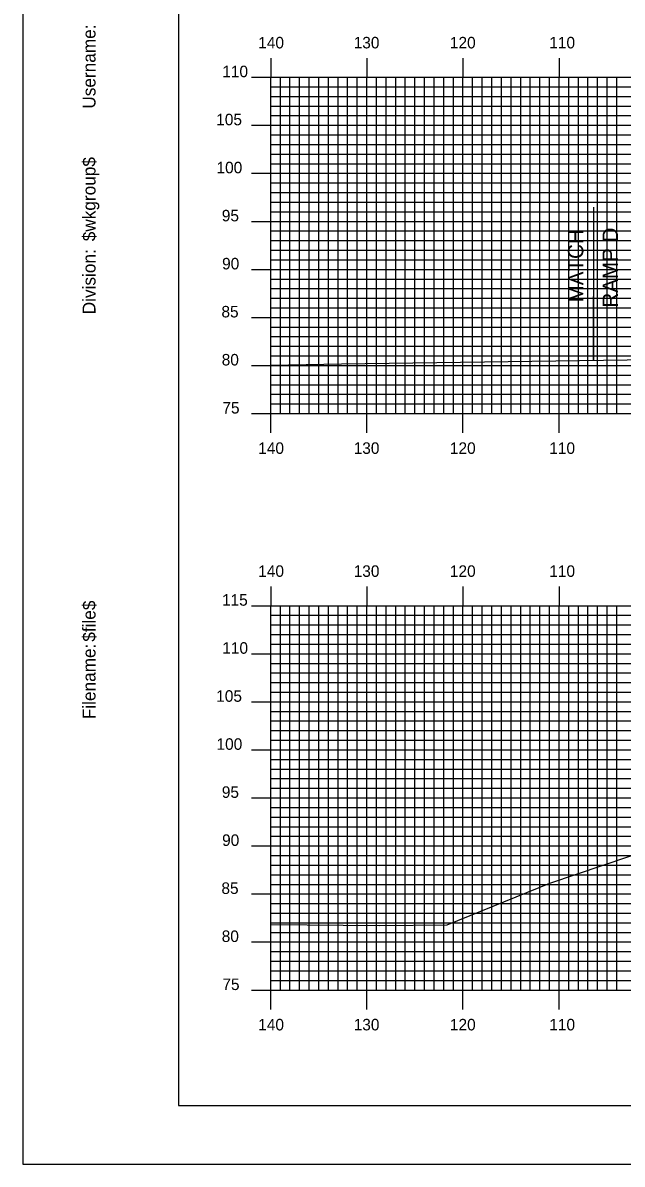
# Model space of a CAD drawing. Extents: x 1755888 to 1756232, y 442591 to 442811.
# Drawn here: x 1755888.3 to 1755950.6, y 442590.5 to 442709.3 of the extents above; entities that cross this region are included whole.
import ezdxf

# ---------------------------------------------------------------- set-up
doc = ezdxf.new("R2010")
doc.units = 0
for name, color, linetype in [('ANNOTATION', 7, 'Continuous'), ('BORDER', 7, 'Continuous'), ('D_Roadway_SubGrade', 7, 'Continuous'), ('H_V ANNOTATION', 7, 'Continuous'), ('MAJOR', 7, 'Continuous'), ('MINOR', 7, 'Continuous'), ('PLOT BOUNDARY', 7, 'Continuous'), ('S_Roadway_Centerline', 7, 'Continuous')]:
    doc.layers.add(name, color=color, linetype=linetype)

msp = doc.modelspace()

# ---------------------------------------------------------------- linework, layer by layer
at = {"layer": 'ANNOTATION'}
msp.add_line((1755947.63, 442674.2), (1755947.63, 442680.86), dxfattribs=at)
at = {"layer": 'BORDER'}
msp.add_lwpolyline([(1755904.46, 442596.67), (1756224.46, 442596.67), (1756224.46, 442806.67), (1755904.46, 442806.67)], close=True, dxfattribs=at)
at = {"layer": 'D_Roadway_SubGrade'}
msp.add_line((1755947.63, 442690.15), (1755947.63, 442674.2), dxfattribs=at)
at = {"layer": 'MAJOR'}
for p, q in [((1755914.06, 442705.67), (1755914.06, 442703.67)), ((1755924.06, 442705.67), (1755924.06, 442703.67)), ((1755934.06, 442705.67), (1755934.06, 442703.67)), ((1755944.06, 442705.67), (1755944.06, 442703.67)), ((1755912.05, 442703.67), (1755914.06, 442703.67)), ((1755914.06, 442703.67), (1756194.06, 442703.67)), ((1755914.06, 442668.67), (1755914.06, 442703.67)), ((1755914.06, 442668.67), (1755914.06, 442703.67)), ((1755914.06, 442703.67), (1756194.06, 442703.67)), ((1755924.06, 442668.67), (1755924.06, 442703.67)), ((1755934.06, 442668.67), (1755934.06, 442703.67)), ((1755944.06, 442668.67), (1755944.06, 442703.67)), ((1755912.05, 442698.67), (1755914.06, 442698.67)), ((1755914.06, 442698.67), (1756194.06, 442698.67)), ((1755912.05, 442693.67), (1755914.06, 442693.67)), ((1755914.06, 442693.67), (1756194.06, 442693.67)), ((1755912.05, 442688.67), (1755914.06, 442688.67)), ((1755914.06, 442688.67), (1756194.06, 442688.67)), ((1755912.05, 442683.67), (1755914.06, 442683.67)), ((1755914.06, 442683.67), (1756194.06, 442683.67)), ((1755912.05, 442678.67), (1755914.06, 442678.67)), ((1755914.06, 442678.67), (1756194.06, 442678.67)), ((1755912.05, 442673.67), (1755914.06, 442673.67)), ((1755914.06, 442673.67), (1756194.06, 442673.67)), ((1755912.05, 442668.67), (1755914.06, 442668.67)), ((1755914.06, 442668.67), (1756194.06, 442668.67)), ((1755914.06, 442668.67), (1756194.06, 442668.67)), ((1755914.06, 442666.66), (1755914.06, 442668.67)), ((1755924.06, 442666.66), (1755924.06, 442668.67)), ((1755934.06, 442666.66), (1755934.06, 442668.67)), ((1755944.06, 442666.66), (1755944.06, 442668.67)), ((1755914.06, 442650.67), (1755914.06, 442648.67)), ((1755924.06, 442650.67), (1755924.06, 442648.67)), ((1755934.06, 442650.67), (1755934.06, 442648.67)), ((1755944.06, 442650.67), (1755944.06, 442648.67)), ((1755912.05, 442648.67), (1755914.06, 442648.67)), ((1755914.06, 442648.67), (1756194.06, 442648.67)), ((1755914.06, 442608.67), (1755914.06, 442648.67)), ((1755914.06, 442608.67), (1755914.06, 442648.67)), ((1755914.06, 442648.67), (1756194.06, 442648.67)), ((1755924.06, 442608.67), (1755924.06, 442648.67)), ((1755934.06, 442608.67), (1755934.06, 442648.67)), ((1755944.06, 442608.67), (1755944.06, 442648.67)), ((1755912.05, 442643.67), (1755914.06, 442643.67)), ((1755914.06, 442643.67), (1756194.06, 442643.67)), ((1755912.05, 442638.67), (1755914.06, 442638.67)), ((1755914.06, 442638.67), (1756194.06, 442638.67)), ((1755912.05, 442633.67), (1755914.06, 442633.67)), ((1755914.06, 442633.67), (1756194.06, 442633.67)), ((1755912.05, 442628.67), (1755914.06, 442628.67)), ((1755914.06, 442628.67), (1756194.06, 442628.67)), ((1755912.05, 442623.67), (1755914.06, 442623.67)), ((1755914.06, 442623.67), (1756194.06, 442623.67)), ((1755912.05, 442618.67), (1755914.06, 442618.67)), ((1755914.06, 442618.67), (1756194.06, 442618.67)), ((1755912.05, 442613.67), (1755914.06, 442613.67)), ((1755914.06, 442613.67), (1756194.06, 442613.67)), ((1755912.05, 442608.67), (1755914.06, 442608.67)), ((1755914.06, 442608.67), (1756194.06, 442608.67)), ((1755914.06, 442608.67), (1756194.06, 442608.67)), ((1755914.06, 442606.66), (1755914.06, 442608.67)), ((1755924.06, 442606.66), (1755924.06, 442608.67)), ((1755934.06, 442606.66), (1755934.06, 442608.67)), ((1755944.06, 442606.66), (1755944.06, 442608.67))]:
    msp.add_line(p, q, dxfattribs=at)
at = {"layer": 'MINOR'}
for p, q in [((1755914.06, 442702.67), (1756194.06, 442702.67)), ((1755914.06, 442702.67), (1755916.06, 442702.67)), ((1755915.06, 442668.67), (1755915.06, 442703.67)), ((1755916.06, 442668.67), (1755916.06, 442703.67)), ((1755917.06, 442668.67), (1755917.06, 442703.67)), ((1755918.06, 442668.67), (1755918.06, 442703.67)), ((1755919.06, 442668.67), (1755919.06, 442703.67)), ((1755920.06, 442668.67), (1755920.06, 442703.67)), ((1755921.06, 442668.67), (1755921.06, 442703.67)), ((1755922.06, 442668.67), (1755922.06, 442703.67)), ((1755923.06, 442668.67), (1755923.06, 442703.67)), ((1755925.06, 442668.67), (1755925.06, 442703.67)), ((1755926.06, 442668.67), (1755926.06, 442703.67)), ((1755927.06, 442668.67), (1755927.06, 442703.67)), ((1755928.06, 442668.67), (1755928.06, 442703.67)), ((1755929.06, 442668.67), (1755929.06, 442703.67)), ((1755930.06, 442668.67), (1755930.06, 442703.67)), ((1755931.06, 442668.67), (1755931.06, 442703.67)), ((1755932.06, 442668.67), (1755932.06, 442703.67)), ((1755933.06, 442668.67), (1755933.06, 442703.67)), ((1755935.06, 442668.67), (1755935.06, 442703.67)), ((1755936.06, 442668.67), (1755936.06, 442703.67)), ((1755937.06, 442668.67), (1755937.06, 442703.67)), ((1755938.06, 442668.67), (1755938.06, 442703.67)), ((1755939.06, 442668.67), (1755939.06, 442703.67)), ((1755940.06, 442668.67), (1755940.06, 442703.67)), ((1755941.06, 442668.67), (1755941.06, 442703.67)), ((1755942.06, 442668.67), (1755942.06, 442703.67)), ((1755943.06, 442668.67), (1755943.06, 442703.67)), ((1755945.06, 442668.67), (1755945.06, 442703.67)), ((1755946.06, 442668.67), (1755946.06, 442703.67)), ((1755947.06, 442668.67), (1755947.06, 442703.67)), ((1755948.06, 442668.67), (1755948.06, 442703.67)), ((1755949.06, 442668.67), (1755949.06, 442703.67)), ((1755950.06, 442668.67), (1755950.06, 442703.67)), ((1755914.06, 442701.67), (1756194.06, 442701.67)), ((1755914.06, 442701.67), (1755916.06, 442701.67)), ((1755914.06, 442700.67), (1756194.06, 442700.67)), ((1755914.06, 442700.67), (1755916.06, 442700.67)), ((1755914.06, 442699.67), (1756194.06, 442699.67)), ((1755914.06, 442699.67), (1755916.06, 442699.67)), ((1755914.06, 442697.67), (1756194.06, 442697.67)), ((1755914.06, 442697.67), (1755916.06, 442697.67)), ((1755914.06, 442696.67), (1756194.06, 442696.67)), ((1755914.06, 442696.67), (1755916.06, 442696.67)), ((1755914.06, 442695.67), (1756194.06, 442695.67)), ((1755914.06, 442695.67), (1755916.06, 442695.67)), ((1755914.06, 442694.67), (1756194.06, 442694.67)), ((1755914.06, 442694.67), (1755916.06, 442694.67)), ((1755914.06, 442692.67), (1756194.06, 442692.67)), ((1755914.06, 442692.67), (1755916.06, 442692.67)), ((1755914.06, 442691.67), (1756194.06, 442691.67)), ((1755914.06, 442691.67), (1755916.06, 442691.67)), ((1755914.06, 442690.67), (1756194.06, 442690.67)), ((1755914.06, 442690.67), (1755916.06, 442690.67)), ((1755914.06, 442689.67), (1756194.06, 442689.67)), ((1755914.06, 442689.67), (1755916.06, 442689.67)), ((1755914.06, 442687.67), (1756194.06, 442687.67)), ((1755914.06, 442687.67), (1755916.06, 442687.67)), ((1755914.06, 442686.67), (1756194.06, 442686.67)), ((1755914.06, 442686.67), (1755916.06, 442686.67)), ((1755914.06, 442685.67), (1756194.06, 442685.67)), ((1755914.06, 442685.67), (1755916.06, 442685.67)), ((1755914.06, 442684.67), (1756194.06, 442684.67)), ((1755914.06, 442684.67), (1755916.06, 442684.67)), ((1755914.06, 442682.67), (1756194.06, 442682.67)), ((1755914.06, 442682.67), (1755916.06, 442682.67)), ((1755914.06, 442681.67), (1756194.06, 442681.67)), ((1755914.06, 442681.67), (1755916.06, 442681.67)), ((1755914.06, 442680.67), (1756194.06, 442680.67)), ((1755914.06, 442680.67), (1755916.06, 442680.67)), ((1755914.06, 442679.67), (1756194.06, 442679.67)), ((1755914.06, 442679.67), (1755916.06, 442679.67)), ((1755914.06, 442677.67), (1756194.06, 442677.67)), ((1755914.06, 442677.67), (1755916.06, 442677.67)), ((1755914.06, 442676.67), (1756194.06, 442676.67)), ((1755914.06, 442676.67), (1755916.06, 442676.67)), ((1755914.06, 442675.67), (1756194.06, 442675.67)), ((1755914.06, 442675.67), (1755916.06, 442675.67)), ((1755914.06, 442674.67), (1756194.06, 442674.67)), ((1755914.06, 442674.67), (1755916.06, 442674.67)), ((1755914.06, 442672.67), (1756194.06, 442672.67)), ((1755914.06, 442672.67), (1755916.06, 442672.67)), ((1755914.06, 442671.67), (1756194.06, 442671.67)), ((1755914.06, 442671.67), (1755916.06, 442671.67)), ((1755914.06, 442670.67), (1756194.06, 442670.67)), ((1755914.06, 442670.67), (1755916.06, 442670.67)), ((1755914.06, 442669.67), (1756194.06, 442669.67)), ((1755914.06, 442669.67), (1755916.06, 442669.67)), ((1755915.06, 442608.67), (1755915.06, 442648.67)), ((1755916.06, 442608.67), (1755916.06, 442648.67)), ((1755917.06, 442608.67), (1755917.06, 442648.67)), ((1755918.06, 442608.67), (1755918.06, 442648.67)), ((1755919.06, 442608.67), (1755919.06, 442648.67)), ((1755920.06, 442608.67), (1755920.06, 442648.67)), ((1755921.06, 442608.67), (1755921.06, 442648.67)), ((1755922.06, 442608.67), (1755922.06, 442648.67)), ((1755923.06, 442608.67), (1755923.06, 442648.67)), ((1755925.06, 442608.67), (1755925.06, 442648.67)), ((1755926.06, 442608.67), (1755926.06, 442648.67)), ((1755927.06, 442608.67), (1755927.06, 442648.67)), ((1755928.06, 442608.67), (1755928.06, 442648.67)), ((1755929.06, 442608.67), (1755929.06, 442648.67)), ((1755930.06, 442608.67), (1755930.06, 442648.67)), ((1755931.06, 442608.67), (1755931.06, 442648.67)), ((1755932.06, 442608.67), (1755932.06, 442648.67)), ((1755933.06, 442608.67), (1755933.06, 442648.67)), ((1755935.06, 442608.67), (1755935.06, 442648.67)), ((1755936.06, 442608.67), (1755936.06, 442648.67)), ((1755937.06, 442608.67), (1755937.06, 442648.67)), ((1755938.06, 442608.67), (1755938.06, 442648.67)), ((1755939.06, 442608.67), (1755939.06, 442648.67)), ((1755940.06, 442608.67), (1755940.06, 442648.67)), ((1755941.06, 442608.67), (1755941.06, 442648.67)), ((1755942.06, 442608.67), (1755942.06, 442648.67)), ((1755943.06, 442608.67), (1755943.06, 442648.67)), ((1755945.06, 442608.67), (1755945.06, 442648.67)), ((1755946.06, 442608.67), (1755946.06, 442648.67)), ((1755947.06, 442608.67), (1755947.06, 442648.67)), ((1755948.06, 442608.67), (1755948.06, 442648.67)), ((1755949.06, 442608.67), (1755949.06, 442648.67)), ((1755950.06, 442608.67), (1755950.06, 442648.67)), ((1755914.06, 442647.67), (1756194.06, 442647.67)), ((1755914.06, 442647.67), (1755916.06, 442647.67)), ((1755914.06, 442646.67), (1756194.06, 442646.67)), ((1755914.06, 442646.67), (1755916.06, 442646.67)), ((1755914.06, 442645.67), (1756194.06, 442645.67)), ((1755914.06, 442645.67), (1755916.06, 442645.67)), ((1755914.06, 442644.67), (1756194.06, 442644.67)), ((1755914.06, 442644.67), (1755916.06, 442644.67)), ((1755914.06, 442642.67), (1756194.06, 442642.67)), ((1755914.06, 442642.67), (1755916.06, 442642.67)), ((1755914.06, 442641.67), (1756194.06, 442641.67)), ((1755914.06, 442641.67), (1755916.06, 442641.67)), ((1755914.06, 442640.67), (1756194.06, 442640.67)), ((1755914.06, 442640.67), (1755916.06, 442640.67)), ((1755914.06, 442639.67), (1756194.06, 442639.67)), ((1755914.06, 442639.67), (1755916.06, 442639.67)), ((1755914.06, 442637.67), (1756194.06, 442637.67)), ((1755914.06, 442637.67), (1755916.06, 442637.67)), ((1755914.06, 442636.67), (1756194.06, 442636.67)), ((1755914.06, 442636.67), (1755916.06, 442636.67)), ((1755914.06, 442635.67), (1756194.06, 442635.67)), ((1755914.06, 442635.67), (1755916.06, 442635.67)), ((1755914.06, 442634.67), (1756194.06, 442634.67)), ((1755914.06, 442634.67), (1755916.06, 442634.67)), ((1755914.06, 442632.67), (1756194.06, 442632.67)), ((1755914.06, 442632.67), (1755916.06, 442632.67)), ((1755914.06, 442631.67), (1756194.06, 442631.67)), ((1755914.06, 442631.67), (1755916.06, 442631.67)), ((1755914.06, 442630.67), (1756194.06, 442630.67)), ((1755914.06, 442630.67), (1755916.06, 442630.67)), ((1755914.06, 442629.67), (1756194.06, 442629.67)), ((1755914.06, 442629.67), (1755916.06, 442629.67)), ((1755914.06, 442627.67), (1756194.06, 442627.67)), ((1755914.06, 442627.67), (1755916.06, 442627.67)), ((1755914.06, 442626.67), (1756194.06, 442626.67)), ((1755914.06, 442626.67), (1755916.06, 442626.67)), ((1755914.06, 442625.67), (1756194.06, 442625.67)), ((1755914.06, 442625.67), (1755916.06, 442625.67)), ((1755914.06, 442624.67), (1756194.06, 442624.67)), ((1755914.06, 442624.67), (1755916.06, 442624.67)), ((1755914.06, 442622.67), (1756194.06, 442622.67)), ((1755914.06, 442622.67), (1755916.06, 442622.67)), ((1755914.06, 442621.67), (1756194.06, 442621.67)), ((1755914.06, 442621.67), (1755916.06, 442621.67)), ((1755914.06, 442620.67), (1756194.06, 442620.67)), ((1755914.06, 442620.67), (1755916.06, 442620.67)), ((1755914.06, 442619.67), (1756194.06, 442619.67)), ((1755914.06, 442619.67), (1755916.06, 442619.67)), ((1755914.06, 442617.67), (1756194.06, 442617.67)), ((1755914.06, 442617.67), (1755916.06, 442617.67)), ((1755914.06, 442616.67), (1756194.06, 442616.67)), ((1755914.06, 442616.67), (1755916.06, 442616.67)), ((1755914.06, 442615.67), (1756194.06, 442615.67)), ((1755914.06, 442615.67), (1755916.06, 442615.67)), ((1755914.06, 442614.67), (1756194.06, 442614.67)), ((1755914.06, 442614.67), (1755916.06, 442614.67)), ((1755914.06, 442612.67), (1756194.06, 442612.67)), ((1755914.06, 442612.67), (1755916.06, 442612.67)), ((1755914.06, 442611.67), (1756194.06, 442611.67)), ((1755914.06, 442611.67), (1755916.06, 442611.67)), ((1755914.06, 442610.67), (1756194.06, 442610.67)), ((1755914.06, 442610.67), (1755916.06, 442610.67)), ((1755914.06, 442609.67), (1756194.06, 442609.67)), ((1755914.06, 442609.67), (1755916.06, 442609.67))]:
    msp.add_line(p, q, dxfattribs=at)
at = {"layer": 'PLOT BOUNDARY'}
msp.add_lwpolyline([(1755888.27, 442590.55), (1756228.27, 442590.55), (1756228.27, 442810.55), (1755888.27, 442810.55)], close=True, dxfattribs=at)
at = {"layer": 'S_Roadway_Centerline'}
for points in [[(1755914.06, 442673.7), (1755921.43, 442673.85), (1755956.11, 442674.32), (1755962.18, 442674.36), (1755963.67, 442674.48), (1755979, 442674.79), (1756000.51, 442678.02), (1756003.6, 442678.56), (1756011.42, 442679.93), (1756013.98, 442680.37)], [(1755914.06, 442615.49), (1755925.39, 442615.38), (1755932.41, 442615.46), (1755943.1, 442619.79), (1755954.08, 442623.5), (1755959.17, 442625.2), (1755966.89, 442626.32), (1755993.82, 442631.63), (1755998.58, 442631.59), (1756012.24, 442631.63)]]:
    msp.add_lwpolyline(points, dxfattribs=at)

# ---------------------------------------------------------------- texts
at = {"layer": 'ANNOTATION'}
for s, p in [('MATCH', (1755946.58, 442680.24)), ('RAMP D', (1755950.18, 442679.7))]:
    msp.add_text(s, height=1.6, rotation=90, dxfattribs=at).set_placement(p)
at = {"layer": 'BORDER'}
for s, p in [('Username:', (1755895.83, 442700.4)), ('Username:', (1755895.83, 442700.4)), ('$wkgroup$', (1755895.83, 442686.6)), ('$wkgroup$', (1755895.83, 442686.6)), ('Division:', (1755895.83, 442679)), ('Division:', (1755895.83, 442679)), ('$file$', (1755895.83, 442644.92)), ('$file$', (1755895.83, 442644.92)), ('Filename:', (1755895.83, 442636.86)), ('Filename:', (1755895.83, 442636.86))]:
    msp.add_text(s, height=1.339, rotation=90, dxfattribs=at).set_placement(p)
at = {"layer": 'H_V ANNOTATION'}
for s, p in [('140', (1755912.76, 442706.67)), ('130', (1755922.69, 442706.67)), ('120', (1755932.7, 442706.67)), ('110', (1755943.04, 442706.67)), ('110', (1755909.02, 442703.67)), ('105', (1755908.39, 442698.67)), ('100', (1755908.42, 442693.67)), ('95', (1755908.97, 442688.67)), ('90', (1755909, 442683.67)), ('85', (1755908.93, 442678.67)), ('80', (1755908.96, 442673.67)), ('75', (1755909.03, 442668.67)), ('140', (1755912.76, 442664.47)), ('130', (1755922.69, 442664.47)), ('120', (1755932.7, 442664.47)), ('110', (1755943.04, 442664.47)), ('140', (1755912.76, 442651.67)), ('130', (1755922.69, 442651.67)), ('120', (1755932.7, 442651.67)), ('110', (1755943.04, 442651.67)), ('115', (1755908.99, 442648.67)), ('110', (1755909.02, 442643.67)), ('105', (1755908.39, 442638.67)), ('100', (1755908.42, 442633.67)), ('95', (1755908.97, 442628.67)), ('90', (1755909, 442623.67)), ('85', (1755908.93, 442618.67)), ('80', (1755908.96, 442613.67)), ('75', (1755909.03, 442608.67)), ('140', (1755912.76, 442604.47)), ('130', (1755922.69, 442604.47)), ('120', (1755932.7, 442604.47)), ('110', (1755943.04, 442604.47))]:
    msp.add_text(s, height=1.2, dxfattribs=at).set_placement(p)
at = {"layer": 'MAJOR'}
for p in [(1755914.05, 442668.67), (1755914.05, 442608.67)]:
    msp.add_text('-', height=0.012, dxfattribs=at).set_placement(p)

doc.saveas('drawing.dxf')
